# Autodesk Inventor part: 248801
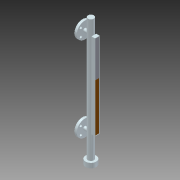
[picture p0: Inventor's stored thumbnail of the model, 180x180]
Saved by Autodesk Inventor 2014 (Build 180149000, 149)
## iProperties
Shininess: 20.0
Length Units: 11272
Angle Units: 11279
Time Units: 11290
Mass Units: 11286
Length Display Precision: 3
Angle Display Precision: 2
Company: Autodesk, Inc.
Created: 2002-07
Part Number: 248801
Project: 2039
Material: Stainless Steel 316
Description: GAUGE, SIGHT LEVEL, 18"
Document SubType Name: Modeling
Designer: Autodesk, Inc.
Density: 8.182 g/cm^3
Mass: 7729.11 g
Surface Area: 1536.75 cm^2
Volume: 944.648 cm^3
Appearance: Stainless Steel
Density: 0.0
Volumn: 0.0
Area: 0.0
PropertySet Name: Model Information
Control State: 0
Master: False
Checked Out: False
Last Check In By: JT
Last Check In Date: 2003-06-20
Title: GAUGE, SIGHT LEVEL 18"
Author: Autodesk, Inc.
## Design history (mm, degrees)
sketch "Sketch1"
  geometry: L1 (0, 0)-(0, 101.6); L2 (0, 0)-(0, -596.9); L3 (15.875, -584.2)-(15.875, 76.2); L4 (15.875, 76.2)-(0, 76.2); L5 (15.875, -457.2)-(0, -457.2); L6 (0, 0)-(15.875, 0); L7 (15.875, -584.2)-(28.575, -584.2); L8 (28.575, -584.2)-(28.575, -609.6); L9 (28.575, -609.6)-(0, -609.6); L10 (0, -609.6)-(0, -596.9)
  constraints: 20 end point, 4 point on line, 3 parallel, 3 perpendicular, 1 collinear, 1 vertical
  dimensions: "d3" = 31.75 diameter of L3 L2; "d6" = 457.2 distance between parallel lines of L5 L6; "d9" = 76.2 distance between parallel lines of L4 L6; "d43" = 25.4 distance of L7.end L8.end; "d44" = 152.4 distance from line of L5.end L9; "d45" = 57.15 diameter of L8 L2
revolve "Revolution1" sketch "Sketch1" stored, may be unused: angle "d10" = 90 deg
sketch "Sketch2"
  geometry: C1 r 9.525 at (0, 0); C2 r 9.525 at (-457.2, 0); 1 further point
  constraints: 2 centre point, 1 coincident, 1 equal radius, 1 horizontal alignment
  dimensions: "d11" = 457.2 distance of C2.centre C1.centre (= d6); "d12" = 19.05 diameter of C2
extrude "Extrusion2" join sketch "Sketch2" distance "d13" = 31.75; taper "d14" = 0 deg
sketch "Sketch3"
  geometry: C1 r 9.525 at (0, 0) reference; C2 r 9.525 at (0, -457.2) reference; C3 r 44.45 at (0, 0); C4 r 44.45 at (0, -457.2)
  constraints: 2 centre point, 2 coincident, 1 equal radius
  dimensions: "d15" = 88.9 diameter of C3
extrude "Extrusion3" join sketch "Sketch3" distance "d16" = 12.7; taper "d17" = 0 deg
sketch "Sketch4"
  geometry: L1 (0, -457.2)-(-21.328, -435.872); L2 (0, -457.2)-(-30.162, -457.2); C1 r 44.45 at (0, 0) reference; C2 r 44.45 at (0, -457.2) reference; A1 r 30.162 centre (0, 0) between (-21.328, 21.328) and (-21.328, -21.328); A2 r 30.162 centre (0, -457.2) between (-21.328, -435.872) and (21.328, -435.872); 4 further points
  constraints: 9 point on circle, 6 vertical alignment, 4 end point, 2 centre point, 2 coincident, 1 horizontal, 1 horizontal alignment
  dimensions: "d18" = 60.325 diameter of A1; "d19" = 60.325 diameter of A2; "d23" = 45 deg angle of L2 L1
hole "Hole1" sketch "Sketch4" at (-21.328, 21.328), (-21.328, -21.328), (21.328, -21.328), (21.328, 21.328), (21.328, -435.872), (21.328, -478.528), (-21.328, -478.528), (-21.328, -435.872) diameter "d24" = 13.49375; stored, may be unused: countersink angle "d28" = 82 deg, drill point angle "d30" = 118 deg; dims "d25" = 12.7, "d26" = 9.525, "d27" = 6.35, "d29" = 19.05
workplane "Work Plane1"
sketch "Sketch5"
  geometry: L1 (63.5, 12.7)-(520.7, 12.7); L2 (520.7, 12.7)-(520.7, -12.7); L3 (520.7, -12.7)-(63.5, -12.7); L4 (63.5, -12.7)-(63.5, 12.7); L5 (520.7, 0)-(63.5, 0); L6 (519.176, 11.176)-(65.024, 11.176); L7 (65.024, 11.176)-(65.024, -11.176); L8 (65.024, -11.176)-(519.176, -11.176); L9 (519.176, -11.176)-(519.176, 11.176); 1 further point
  constraints: 18 end point, 4 parallel, 2 midpoint, 2 perpendicular, 1 horizontal, 1 point on line, 3 other
  dimensions: "d31" = 1.524 distance between parallel lines of L1 L6; "d32" = 25.4 distance of L3.end L1.start; "d33" = 0 distance from line of L2 point (520.7, 0); "d34" = 457.2 distance of L2.end L3.end
extrude "Extrusion4" join sketch "Sketch5" distance "d35" = 19.05; taper "d36" = 0 deg
sketch "Sketch6"
  geometry: L1 (11.176, 519.176)-(11.176, 65.024) reference; L2 (-11.176, 519.176)-(-11.176, 65.024) reference; L3 (-11.176, 65.024)-(11.176, 65.024) reference; L4 (11.176, 519.176)-(-11.176, 519.176) reference
extrude "Extrusion5" join sketch "Sketch6" distance "d37" = 4.7625; taper "d38" = 0 deg
sketch "Sketch7"
  geometry: L1 (-11.176, 65.024)-(-11.176, 519.176) reference; L2 (11.176, 65.024)-(-11.176, 65.024) reference; L3 (11.176, 519.176)-(11.176, 65.024) reference; L4 (11.176, 323.066)-(-11.176, 323.066)
  constraints: 2 end point, 2 point on line, 1 perpendicular
extrude "Extrusion6" join sketch "Sketch7" distance "d39" = 12.7; taper "d40" = 0 deg
sketch "Sketch8"
  geometry: L1 (-11.176, 323.066)-(11.176, 323.066) reference; L2 (11.176, 519.176)-(11.176, 323.066) reference; L3 (-11.176, 519.176)-(11.176, 519.176) reference; L4 (-11.176, 323.066)-(-11.176, 519.176) reference
extrude "Extrusion7" join sketch "Sketch8" distance "d41" = 12.446; taper "d42" = 0 deg
body "Solid1"
